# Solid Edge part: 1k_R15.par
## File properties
Author: Türk
Template: Iso Part.par
Last saved by: Türk
Revision: 5
Application: Solid Edge
Accuracy: 0,990
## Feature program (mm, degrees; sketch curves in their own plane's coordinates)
pattern "PatternOccurrence_2"  XOffset = 18.9474 deg
pattern "PatternOccurrence_3"  XCount = 19; XOffset = 18.9474 deg
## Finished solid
Body 1: solid body, 117 faces, 344 edges, 228 vertices.
  Faces by surface: plane 78, cylinder 39
  Edges by curve: line 266, circle 78
Bounding box of the edges (mm): 37.957 x 30.000 x 37.839, from (-18.9785, 0, -19) to (18.9785, 30, 18.839).
Cylindrical faces by radius (mm): R14 x1, R15 x19, R19 x19
Planar faces by outward normal: +y 1, -y 1, -z 2, oblique 74
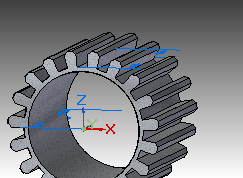
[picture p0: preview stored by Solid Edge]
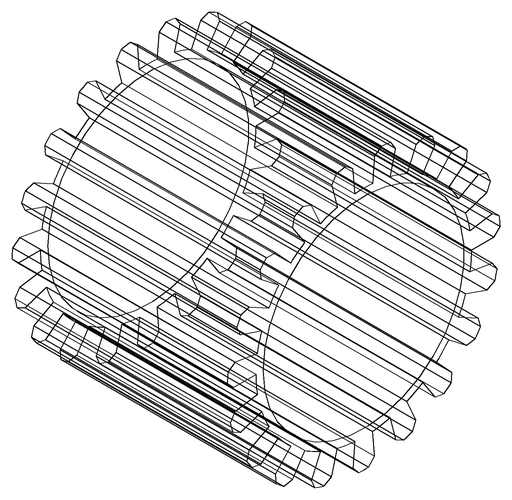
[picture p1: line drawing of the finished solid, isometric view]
